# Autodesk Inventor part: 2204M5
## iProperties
Shininess: 40.0
Length Units: 11269
Angle Units: 11279
Time Units: 11290
Mass Units: 11284
Length Display Precision: 3
Angle Display Precision: 2
Compacted: True
Company: Pneumax S.p.A.
Part Number: 2204M5
Material: Default
Description: GOMITO GIREVOLE Ø4 M5
Document SubType Name: Modellazione
Catalog Web Link: www.pneumaxspa.com
Density: 1.59
Volumn: 0.8648857994912436
Area: 17.092995283760587
PropertySet Name: Model Information
Control State: 0
Master: False
Checked Out: False
Revision Number: 0
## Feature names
1. Revolution6
2. Revolution12
3. Revolution7
4. Revolution11
5. Hole9
6. Revolution9
7. Extrusion11
8. Circular Pattern8
9. Hole7
10. Chamfer10
11. REV_M5 [Revolution]
12. Revolution8
13. FORO_M5 [Hole]
14. ESTRU_M5 [Extrusion]
15. ARRY_M5 [Circular Pattern]
16. FORO_M52 [Hole]
17. SMM5 [Chamfer]
